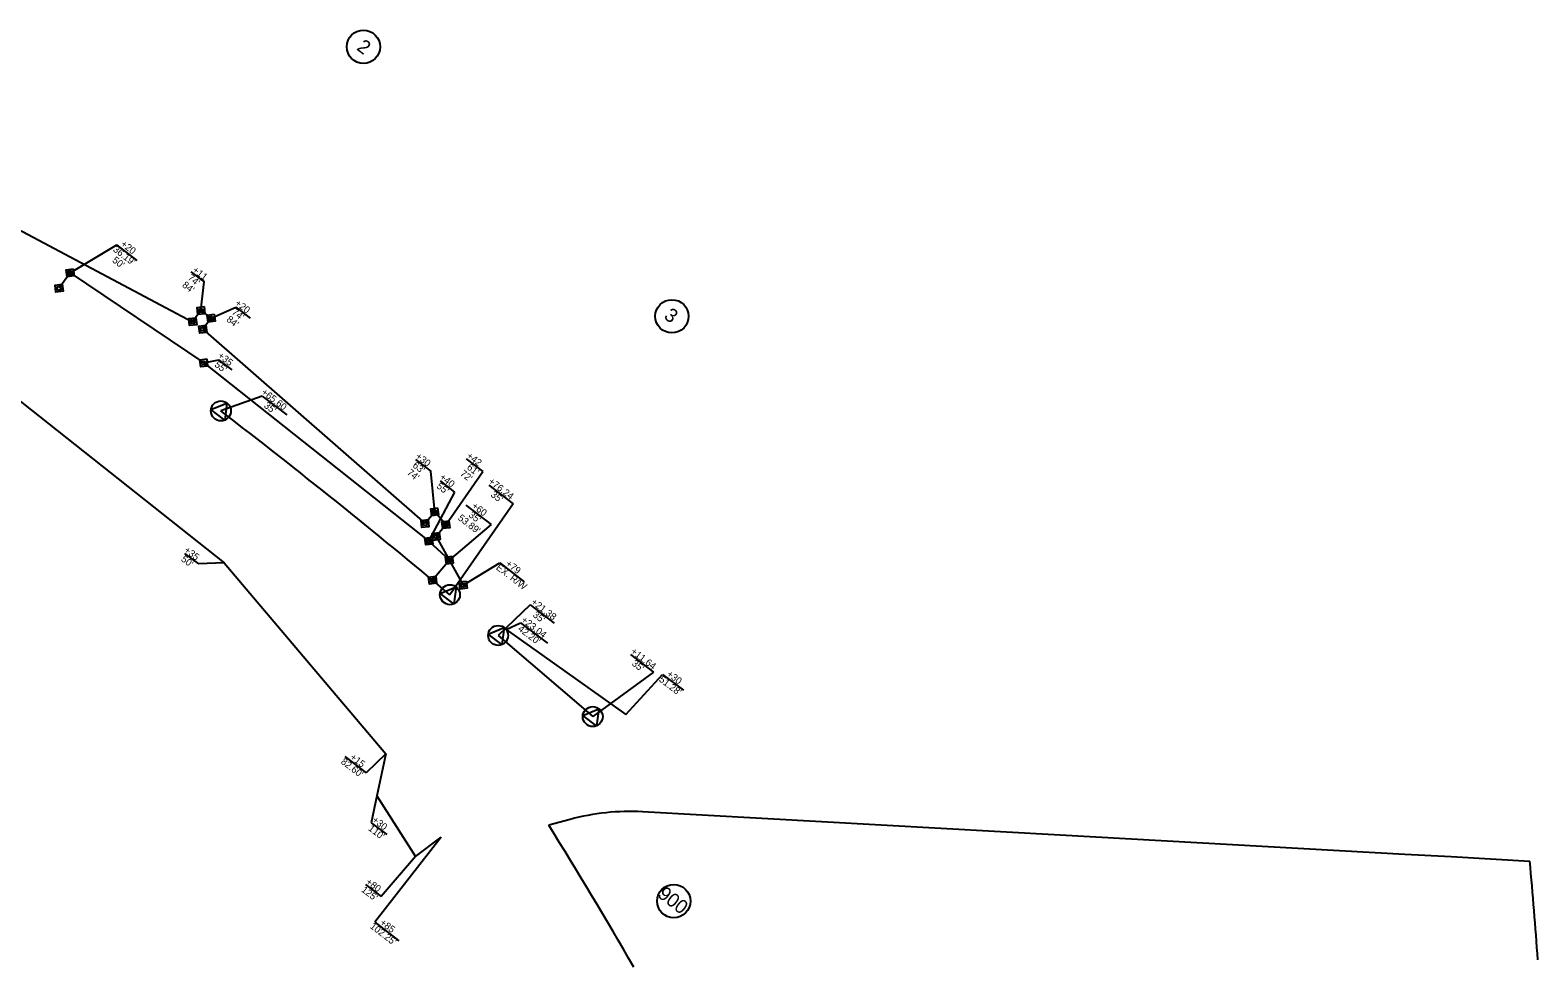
# Model space of a CAD drawing. Extents: x 1618217 to 1621927, y 897445 to 899141.
# Drawn here: x 1618900 to 1619989, y 898081 to 898752 of the extents above; entities that cross this region are included whole.
import ezdxf

# ---------------------------------------------------------------- set-up
doc = ezdxf.new("R2010")
doc.units = 0
for name, color, linetype in [('Prop Easement Construction', 7, 'Continuous'), ('Prop Easement Construction Station Offsets', 7, 'Continuous'), ('Prop Easement Permanent Drainage Utility', 7, 'Continuous'), ('Prop Easement Permanent Drainage Utility Station Offsets', 7, 'Continuous'), ('Prop Easement Permanent Utility', 7, 'Continuous'), ('Prop Easement Permanent Utility Station Offsets', 7, 'Continuous'), ('Prop Parcel Number CELL', 7, 'Continuous'), ('Prop ROW Marker CELL', 7, 'Continuous'), ('Prop ROW Permanent Easement CELL', 7, 'Continuous'), ('Prop ROW RW Lines', 7, 'Continuous'), ('Prop ROW Station Offsets', 7, 'Continuous'), ('Scratch_Level_3', 7, 'Continuous')]:
    doc.layers.add(name, color=color, linetype=linetype)

msp = doc.modelspace()

# ---------------------------------------------------------------- linework, layer by layer
at = {"layer": 'Prop Easement Construction'}
for p, q in [((1618836.3, 898528.9), (1619039.9, 898367.7)), ((1619039.9, 898367.7), (1619156.6, 898229.9)), ((1619243.6, 898319.7), (1619329.8, 898258.2)), ((1619156.6, 898229.9), (1619150, 898199.5)), ((1619150, 898199.5), (1619178, 898155.7)), ((1619178, 898155.7), (1619196.6, 898169.7))]:
    msp.add_line(p, q, dxfattribs=at)
at = {"layer": 'Prop Easement Construction Station Offsets'}
for p, q in [((1619011.2, 898374.5), (1619021.2, 898366.9)), ((1619039.9, 898367.7), (1619021.2, 898366.9)), ((1619243.6, 898319.7), (1619253.9, 898324.5)), ((1619253.9, 898324.5), (1619273.3, 898309.7)), ((1619329.8, 898258.2), (1619356.4, 898287.2)), ((1619356.4, 898287.2), (1619371.5, 898275.7)), ((1619156.6, 898229.9), (1619142.5, 898216)), ((1619127, 898227.8), (1619142.5, 898216)), ((1619150, 898199.5), (1619146.1, 898180.1)), ((1619146.1, 898180.1), (1619157.3, 898171.5)), ((1619196.6, 898169.7), (1619148.7, 898108.3)), ((1619178, 898155.7), (1619153.2, 898126.8)), ((1619141.8, 898135.6), (1619153.2, 898126.8)), ((1619148.7, 898108.3), (1619166.1, 898094.9))]:
    msp.add_line(p, q, dxfattribs=at)
at = {"layer": 'Prop Easement Permanent Drainage Utility'}
for p, q in [((1618928.7, 898577.1), (1618920.6, 898565.9)), ((1618928.7, 898577.1), (1619025.1, 898512)), ((1619025.1, 898512), (1619187.6, 898383.4)), ((1619187.6, 898383.4), (1619202.5, 898369.7)), ((1619202.5, 898369.7), (1619190.4, 898355.1))]:
    msp.add_line(p, q, dxfattribs=at)
at = {"layer": 'Prop Easement Permanent Drainage Utility Station Offsets'}
for p, q in [((1618928.7, 898577.1), (1618962.4, 898597.4)), ((1618977.1, 898586.1), (1618962.4, 898597.4)), ((1619025.1, 898512), (1619036.1, 898514.3)), ((1619045.7, 898507), (1619036.1, 898514.3)), ((1619206.4, 898418.8), (1619196, 898426.8)), ((1619187.6, 898383.4), (1619206.4, 898418.8)), ((1619232.8, 898395.5), (1619214.6, 898409.4)), ((1619202.5, 898369.7), (1619232.8, 898395.5))]:
    msp.add_line(p, q, dxfattribs=at)
at = {"layer": 'Prop Easement Permanent Utility'}
for p, q in [((1618878.9, 898615.1), (1619017.1, 898541.8)), ((1619023.1, 898549.8), (1619017.1, 898541.8)), ((1619023.1, 898549.8), (1619030.4, 898544.3)), ((1619030.4, 898544.3), (1619024.4, 898536.3)), ((1619024.4, 898536.3), (1619184.9, 898396)), ((1619191.9, 898404.5), (1619184.9, 898396)), ((1619200, 898395.2), (1619191.9, 898404.5)), ((1619200, 898395.2), (1619193, 898386.8)), ((1619193, 898386.8), (1619212.4, 898351.7))]:
    msp.add_line(p, q, dxfattribs=at)
at = {"layer": 'Prop Easement Permanent Utility Station Offsets'}
for p, q in [((1619015.9, 898577.8), (1619025.4, 898570.5)), ((1619023.1, 898549.8), (1619025.4, 898570.5)), ((1619030.4, 898544.3), (1619048.3, 898552.3)), ((1619048.3, 898552.3), (1619058.7, 898544.3)), ((1619178.1, 898442.2), (1619189, 898433.9)), ((1619214.7, 898442.8), (1619226.6, 898433.7)), ((1619191.9, 898404.5), (1619189, 898433.9)), ((1619200, 898395.2), (1619226.6, 898433.7)), ((1619212.4, 898351.7), (1619238.9, 898367.7)), ((1619238.9, 898367.7), (1619256.6, 898354.1))]:
    msp.add_line(p, q, dxfattribs=at)
at = {"layer": 'Prop Parcel Number CELL'}
for p, q in [((1619140.4, 898740.3), (1619140.4, 898740.3)), ((1619363.2, 898545.7), (1619363.2, 898545.7)), ((1619364.5, 898123.5), (1619364.5, 898123.5))]:
    msp.add_line(p, q, dxfattribs=at)
for centre in [(1619140.4, 898740.3), (1619363.2, 898545.7), (1619364.5, 898123.5)]:
    msp.add_circle(centre, 12, dxfattribs=at)
at = {"layer": 'Prop ROW Marker CELL'}
for p, q in [((1618928.7, 898577.1), (1618928.7, 898577.1)), ((1618920.6, 898565.9), (1618920.6, 898565.9)), ((1619023.1, 898549.8), (1619023.1, 898549.8)), ((1619017.1, 898541.8), (1619017.1, 898541.8)), ((1619024.4, 898536.3), (1619024.4, 898536.3)), ((1619030.4, 898544.3), (1619030.4, 898544.3)), ((1619025.1, 898512), (1619025.1, 898512)), ((1619037.5, 898477.4), (1619037.5, 898477.4)), ((1619191.9, 898404.5), (1619191.9, 898404.5)), ((1619184.9, 898396), (1619184.9, 898396)), ((1619200, 898395.2), (1619200, 898395.2)), ((1619187.6, 898383.4), (1619187.6, 898383.4)), ((1619193, 898386.8), (1619193, 898386.8)), ((1619202.5, 898369.7), (1619202.5, 898369.7)), ((1619190.4, 898355.1), (1619190.4, 898355.1)), ((1619212.4, 898351.7), (1619212.4, 898351.7)), ((1619202.9, 898344.7), (1619202.9, 898344.7)), ((1619237.7, 898315.3), (1619237.7, 898315.3)), ((1619306, 898256.7), (1619306, 898256.7))]:
    msp.add_line(p, q, dxfattribs=at)
for points in [[(1619030.3, 898478.3), (1619041.9, 898483.1), (1619040.3, 898470.7)], [(1619195.8, 898345.6), (1619207.3, 898350.4), (1619205.7, 898338)], [(1619230.5, 898316.3), (1619242, 898321), (1619240.4, 898308.7)], [(1619298.9, 898257.6), (1619310.4, 898262.4), (1619308.8, 898250)]]:
    msp.add_lwpolyline(points, close=True, dxfattribs=at)
for centre in [(1619037.5, 898477.4), (1619202.9, 898344.7), (1619237.7, 898315.3), (1619306, 898256.7)]:
    msp.add_circle(centre, 7.2, dxfattribs=at)
at = {"layer": 'Prop ROW Permanent Easement CELL'}
for points in [[(1618930.9, 898580), (1618931.6, 898574.9), (1618926.5, 898574.3), (1618925.8, 898579.3)], [(1618929.8, 898578.6), (1618930.1, 898576), (1618927.6, 898575.7), (1618927.3, 898578.2)], [(1618922.8, 898568.8), (1618923.5, 898563.8), (1618918.4, 898563.1), (1618917.8, 898568.1)], [(1618921.7, 898567.4), (1618922, 898564.9), (1618919.5, 898564.5), (1618919.2, 898567)], [(1619025.3, 898552.7), (1619026, 898547.6), (1619020.9, 898547), (1619020.3, 898552)], [(1619024.2, 898551.2), (1619024.5, 898548.7), (1619022, 898548.4), (1619021.7, 898550.9)], [(1619032.6, 898547.2), (1619033.3, 898542.1), (1619028.2, 898541.5), (1619027.6, 898546.5)], [(1619031.5, 898545.7), (1619031.9, 898543.2), (1619029.3, 898542.9), (1619029, 898545.4)], [(1619019.3, 898544.7), (1619020, 898539.6), (1619014.9, 898539), (1619014.3, 898544)], [(1619018.2, 898543.2), (1619018.5, 898540.7), (1619016, 898540.4), (1619015.7, 898542.9)], [(1619026.6, 898539.2), (1619027.3, 898534.1), (1619022.2, 898533.5), (1619021.6, 898538.5)], [(1619025.5, 898537.8), (1619025.8, 898535.2), (1619023.3, 898534.9), (1619023, 898537.4)], [(1619027.3, 898514.9), (1619027.9, 898509.8), (1619022.9, 898509.1), (1619022.2, 898514.2)], [(1619026.2, 898513.4), (1619026.5, 898510.9), (1619024, 898510.6), (1619023.6, 898513.1)], [(1619194, 898407.4), (1619194.7, 898402.3), (1619189.7, 898401.7), (1619189, 898406.7)], [(1619193, 898406), (1619193.3, 898403.4), (1619190.8, 898403.1), (1619190.4, 898405.6)], [(1619187.1, 898398.9), (1619187.7, 898393.8), (1619182.7, 898393.2), (1619182, 898398.2)], [(1619186, 898397.5), (1619186.3, 898394.9), (1619183.8, 898394.6), (1619183.4, 898397.1)], [(1619202.2, 898398.1), (1619202.8, 898393.1), (1619197.8, 898392.4), (1619197.1, 898397.4)], [(1619201.1, 898396.7), (1619201.4, 898394.1), (1619198.9, 898393.8), (1619198.6, 898396.3)], [(1619189.8, 898386.3), (1619190.5, 898381.2), (1619185.4, 898380.6), (1619184.7, 898385.6)], [(1619188.7, 898384.8), (1619189, 898382.3), (1619186.5, 898382), (1619186.2, 898384.5)], [(1619195.2, 898389.6), (1619195.8, 898384.6), (1619190.8, 898383.9), (1619190.1, 898388.9)], [(1619194.1, 898388.2), (1619194.4, 898385.7), (1619191.9, 898385.3), (1619191.5, 898387.9)], [(1619204.6, 898372.5), (1619205.3, 898367.5), (1619200.3, 898366.8), (1619199.6, 898371.9)], [(1619203.6, 898371.1), (1619203.9, 898368.6), (1619201.4, 898368.2), (1619201, 898370.8)], [(1619192.6, 898358), (1619193.2, 898353), (1619188.2, 898352.3), (1619187.5, 898357.3)], [(1619191.5, 898356.6), (1619191.8, 898354.1), (1619189.3, 898353.7), (1619189, 898356.2)], [(1619214.6, 898354.5), (1619215.3, 898349.5), (1619210.2, 898348.8), (1619209.6, 898353.9)], [(1619213.5, 898353.1), (1619213.9, 898350.6), (1619211.3, 898350.2), (1619211, 898352.8)]]:
    msp.add_lwpolyline(points, close=True, dxfattribs=at)
at = {"layer": 'Prop ROW RW Lines'}
msp.add_line((1619237.7, 898315.3), (1619306, 898256.7), dxfattribs=at)
msp.add_arc((1615970.5, 894484.3), 5035, 50.0598, 52.4737, dxfattribs=at)
at = {"layer": 'Prop ROW Station Offsets'}
for p, q in [((1619067.2, 898488.1), (1619037.5, 898477.4)), ((1619067.2, 898488.1), (1619085.1, 898474.5)), ((1619231, 898423.7), (1619248.5, 898410.3)), ((1619248.5, 898410.3), (1619202.9, 898344.7)), ((1619260.9, 898337.4), (1619237.7, 898315.3)), ((1619260.9, 898337.4), (1619278.2, 898324.2)), ((1619333.3, 898301.5), (1619349.8, 898288.9)), ((1619349.8, 898288.9), (1619306, 898256.7))]:
    msp.add_line(p, q, dxfattribs=at)
at = {"layer": 'Scratch_Level_3'}
for p, q in [((1619289.6, 898182.5), (1619274.2, 898178.3)), ((1619982.7, 898152.2), (1619925.9, 898155.4))]:
    msp.add_line(p, q, dxfattribs=at)
msp.add_lwpolyline([(1619925.9, 898155.4), (1619892.4, 898157.2), (1619643.5, 898171.1), (1619342, 898188)], dxfattribs=at)
for centre, radius, start, end in [((1619332.8, 898023.2), 165, 86.8045, 105.1672), ((1616896.2, 896683.3), 2808.9, 29.7184, 32.1569), ((1615052, 897716.2), 4950, 4.2279, 5.0535)]:
    msp.add_arc(centre, radius, start, end, dxfattribs=at)

# ---------------------------------------------------------------- texts
at = {"layer": 'Prop Easement Construction Station Offsets'}
for s, p in [("50'", (1619008.3, 898369.5)), ('+35', (1619010.5, 898376)), ('+23.04', (1619253.9, 898325.6)), ("42.20'", (1619251.6, 898319.2)), ("51.28'", (1619353.4, 898282.6)), ('+30', (1619359, 898286.5)), ("82.60'", (1619123.7, 898223.3)), ('+15', (1619130.3, 898226.5)), ("110'", (1619143.5, 898175.1)), ('+30', (1619146.3, 898181.2)), ("125'", (1619138.5, 898130.8)), ('+80', (1619141.7, 898136.5)), ("102.25'", (1619144.7, 898104.5)), ('+85', (1619151.9, 898107.1))]:
    msp.add_text(s, height=5, rotation=322.554, dxfattribs=at).set_placement(p)
at = {"layer": 'Prop Easement Permanent Drainage Utility Station Offsets'}
for s, p in [("50'", (1618958.6, 898585.3)), ("36.19'", (1618959.1, 898593.1)), ('+20', (1618964.7, 898597)), ("55'", (1619032.5, 898509.9)), ('+35', (1619034.8, 898516.4)), ("55'", (1619192.8, 898422.2)), ('+40', (1619195, 898428.7)), ("35'", (1619216, 898401.4)), ('+60', (1619218.2, 898407.9)), ("53.89'", (1619208.2, 898399.2))]:
    msp.add_text(s, height=5, rotation=322.554, dxfattribs=at).set_placement(p)
at = {"layer": 'Prop Easement Permanent Utility Station Offsets'}
for s, p in [('+11', (1619016.5, 898578.2)), ("84'", (1619009.1, 898567.4)), ("74'", (1619013.1, 898572.6)), ('+20', (1619047.2, 898554.3)), ("84'", (1619041.1, 898542.6)), ("74'", (1619045, 898547.8)), ("63'", (1619175.5, 898437.2)), ('+30', (1619177.6, 898443.7)), ("61'", (1619214.7, 898435.8)), ('+42', (1619214.5, 898444.1)), ("74'", (1619171.5, 898432)), ("72'", (1619209.8, 898431.3)), ('EX. R/W', (1619235.7, 898363.4)), ('+79', (1619242.7, 898366.2))]:
    msp.add_text(s, height=5, rotation=322.554, dxfattribs=at).set_placement(p)
at = {"layer": 'Prop Parcel Number CELL'}
for s, p in [('2', (1619134.9, 898738.6)), ('3', (1619356.8, 898544.7)), ('900', (1619352.2, 898127))]:
    msp.add_text(s, height=10, rotation=322.554, dxfattribs=at).set_placement(p)
at = {"layer": 'Prop ROW Station Offsets'}
for s, p in [('+65.60', (1619066.3, 898490)), ("35'", (1619068.1, 898480.4)), ('+76.24', (1619230.2, 898425.6)), ("35'", (1619231.9, 898416.1)), ('+21.38', (1619261, 898338.5)), ("35'", (1619262.3, 898329.3)), ("35'", (1619333.8, 898294.2)), ('+11.64', (1619333, 898302.9))]:
    msp.add_text(s, height=5, rotation=322.554, dxfattribs=at).set_placement(p)

doc.saveas('drawing.dxf')
